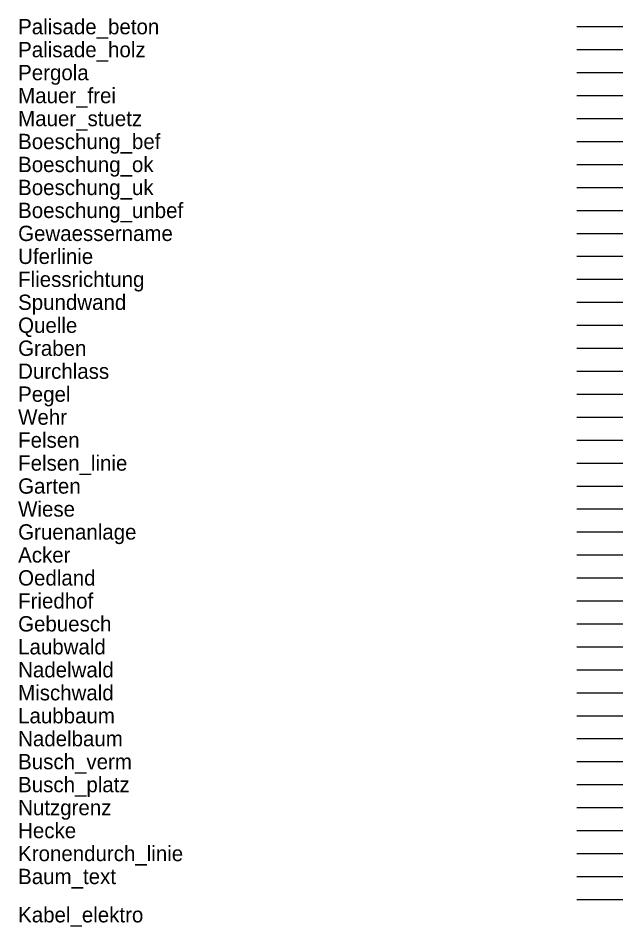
# Model space of a CAD drawing. Extents: x 0 to 177, y -135 to 1.
# Drawn here: x 83.5 to 123, y -58.8 to 0.6 of the extents above; entities that cross this region are included whole.
import ezdxf

# ---------------------------------------------------------------- set-up
doc = ezdxf.new("R2010")
doc.units = 0
for name, color, linetype in [('Acker', 7, 'Continuous'), ('Auslauf_schacht', 7, 'Continuous'), ('Baum_text', 7, 'Continuous'), ('Be_entlueftung', 7, 'Continuous'), ('Beobrohr_gw', 7, 'Continuous'), ('Boeschung_bef', 7, 'Continuous'), ('Boeschung_ok', 7, 'Continuous'), ('Boeschung_uk', 7, 'Continuous'), ('Boeschung_unbef', 7, 'Continuous'), ('Brunnen_eckig', 7, 'Continuous'), ('Brunnen_linie', 7, 'Continuous'), ('Brunnen_rund', 7, 'Continuous'), ('Busch_platz', 7, 'Continuous'), ('Busch_verm', 7, 'Continuous'), ('Durchlass', 7, 'Continuous'), ('Einlauf', 7, 'Continuous'), ('Einlauf_schacht', 7, 'Continuous'), ('Felsen', 7, 'Continuous'), ('Felsen_linie', 7, 'Continuous'), ('Fliessrichtung', 7, 'Continuous'), ('Friedhof', 7, 'Continuous'), ('Garten', 7, 'Continuous'), ('Gebuesch', 7, 'Continuous'), ('Gewaessername', 7, 'Continuous'), ('Graben', 7, 'Continuous'), ('Gruenanlage', 7, 'Continuous'), ('Gully', 7, 'Continuous'), ('Gullyrinne', 7, 'Continuous'), ('Hecke', 7, 'Continuous'), ('Kabel_elektro', 7, 'Continuous'), ('Klaeranlage', 7, 'Continuous'), ('Kronendurch_linie', 7, 'Continuous'), ('Laubbaum', 7, 'Continuous'), ('Laubwald', 7, 'Continuous'), ('Mauer_frei', 7, 'Continuous'), ('Mauer_stuetz', 7, 'Continuous'), ('Merkstein_wasser', 7, 'Continuous'), ('Mischwald', 7, 'Continuous'), ('Nadelbaum', 7, 'Continuous'), ('Nadelwald', 7, 'Continuous'), ('Nutzgrenz', 7, 'Continuous'), ('Oberflurhydrant', 7, 'Continuous'), ('Oedland', 7, 'Continuous'), ('Palisade_beton', 7, 'Continuous'), ('Palisade_holz', 7, 'Continuous'), ('Pegel', 7, 'Continuous'), ('Pergola', 7, 'Continuous'), ('Pfeil_abwasser', 7, 'Continuous'), ('Pfeil_brauchwasser', 7, 'Continuous'), ('Pfeil_regenwasser', 7, 'Continuous'), ('Pfeil_trinkwasser', 7, 'Continuous'), ('Pumpe', 7, 'Continuous'), ('Quelle', 7, 'Continuous'), ('Rohr_abwa', 7, 'Continuous'), ('Rohr_rewa', 7, 'Continuous'), ('Rohr_triwa', 7, 'Continuous'), ('Schacht_e_wasser', 7, 'Continuous'), ('Schacht_r_wasser', 7, 'Continuous'), ('Schieber_wasser', 7, 'Continuous'), ('Schrift_w', 7, 'Continuous'), ('Schrift_wb', 7, 'Continuous'), ('Schutzrohr_triwa', 7, 'Continuous'), ('Sohle_schacht', 7, 'Continuous'), ('Sonstiges_wasser', 7, 'Continuous'), ('Springbrunnen', 7, 'Continuous'), ('Spundwand', 7, 'Continuous'), ('Text_gullyrinne', 7, 'Continuous'), ('Text_rohr_abwa', 7, 'Continuous'), ('Text_rohr_rewa', 7, 'Continuous'), ('Text_rohr_triwa', 7, 'Continuous'), ('Text_schutzrohr_triwa', 7, 'Continuous'), ('Uferlinie', 7, 'Continuous'), ('Unterflurhydrant', 7, 'Continuous'), ('Wasserbehaelter_eckig', 7, 'Continuous'), ('Wasserbehaelter_rund', 7, 'Continuous'), ('Wehr', 7, 'Continuous'), ('Wiese', 7, 'Continuous'), ('Zapfstelle', 7, 'Continuous')]:
    doc.layers.add(name, color=color, linetype=linetype)

msp = doc.modelspace()

# ---------------------------------------------------------------- linework, layer by layer
at = {"layer": 'Auslauf_schacht'}
msp.add_line((120, -48), (123, -48), dxfattribs=at)
at = {"layer": 'Be_entlueftung'}
msp.add_line((120, -19.5), (123, -19.5), dxfattribs=at)
at = {"layer": 'Beobrohr_gw'}
msp.add_line((120, -18), (123, -18), dxfattribs=at)
at = {"layer": 'Brunnen_eckig'}
msp.add_line((120, -36), (123, -36), dxfattribs=at)
at = {"layer": 'Brunnen_linie'}
msp.add_line((120, -33), (123, -33), dxfattribs=at)
at = {"layer": 'Brunnen_rund'}
msp.add_line((120, -34.5), (123, -34.5), dxfattribs=at)
at = {"layer": 'Einlauf'}
msp.add_line((120, -28.5), (123, -28.5), dxfattribs=at)
at = {"layer": 'Einlauf_schacht'}
msp.add_line((120, -46.5), (123, -46.5), dxfattribs=at)
at = {"layer": 'Gully'}
msp.add_line((120, -27), (123, -27), dxfattribs=at)
at = {"layer": 'Gullyrinne'}
msp.add_line((120, -30), (123, -30), dxfattribs=at)
at = {"layer": 'Klaeranlage'}
msp.add_line((120, -43.5), (123, -43.5), dxfattribs=at)
at = {"layer": 'Merkstein_wasser'}
msp.add_line((120, -6), (123, -6), dxfattribs=at)
at = {"layer": 'Oberflurhydrant'}
msp.add_line((120, -12), (123, -12), dxfattribs=at)
at = {"layer": 'Pfeil_abwasser'}
msp.add_line((120, -45), (123, -45), dxfattribs=at)
at = {"layer": 'Pfeil_brauchwasser'}
msp.add_line((120, -54), (123, -54), dxfattribs=at)
at = {"layer": 'Pfeil_regenwasser'}
msp.add_line((120, -55.5), (123, -55.5), dxfattribs=at)
at = {"layer": 'Pfeil_trinkwasser'}
msp.add_line((120, -9), (123, -9), dxfattribs=at)
at = {"layer": 'Pumpe'}
msp.add_line((120, -39), (123, -39), dxfattribs=at)
at = {"layer": 'Rohr_abwa'}
msp.add_line((120, -40.5), (123, -40.5), dxfattribs=at)
at = {"layer": 'Rohr_rewa'}
msp.add_line((120, -51), (123, -51), dxfattribs=at)
at = {"layer": 'Rohr_triwa'}
msp.add_line((120, 0), (123, 0), dxfattribs=at)
at = {"layer": 'Schacht_e_wasser'}
msp.add_line((120, -16.5), (123, -16.5), dxfattribs=at)
at = {"layer": 'Schacht_r_wasser'}
msp.add_line((120, -15), (123, -15), dxfattribs=at)
at = {"layer": 'Schieber_wasser'}
msp.add_line((120, -10.5), (123, -10.5), dxfattribs=at)
at = {"layer": 'Schrift_w'}
msp.add_line((120, -7.5), (123, -7.5), dxfattribs=at)
at = {"layer": 'Schrift_wb'}
msp.add_line((120, -25.5), (123, -25.5), dxfattribs=at)
at = {"layer": 'Schutzrohr_triwa'}
msp.add_line((120, -3), (123, -3), dxfattribs=at)
at = {"layer": 'Sohle_schacht'}
msp.add_line((120, -49.5), (123, -49.5), dxfattribs=at)
at = {"layer": 'Sonstiges_wasser'}
msp.add_line((120, -57), (123, -57), dxfattribs=at)
at = {"layer": 'Springbrunnen'}
msp.add_line((120, -37.5), (123, -37.5), dxfattribs=at)
at = {"layer": 'Text_gullyrinne'}
msp.add_line((120, -31.5), (123, -31.5), dxfattribs=at)
at = {"layer": 'Text_rohr_abwa'}
msp.add_line((120, -42), (123, -42), dxfattribs=at)
at = {"layer": 'Text_rohr_rewa'}
msp.add_line((120, -52.5), (123, -52.5), dxfattribs=at)
at = {"layer": 'Text_rohr_triwa'}
msp.add_line((120, -1.5), (123, -1.5), dxfattribs=at)
at = {"layer": 'Text_schutzrohr_triwa'}
msp.add_line((120, -4.5), (123, -4.5), dxfattribs=at)
at = {"layer": 'Unterflurhydrant'}
msp.add_line((120, -13.5), (123, -13.5), dxfattribs=at)
at = {"layer": 'Wasserbehaelter_eckig'}
msp.add_line((120, -24), (123, -24), dxfattribs=at)
at = {"layer": 'Wasserbehaelter_rund'}
msp.add_line((120, -22.5), (123, -22.5), dxfattribs=at)
at = {"layer": 'Zapfstelle'}
msp.add_line((120, -21), (123, -21), dxfattribs=at)

# ---------------------------------------------------------------- texts
at = {"layer": 'Acker'}
msp.add_text('Acker', height=1, dxfattribs=at).set_placement((83.5, -35))
at = {"layer": 'Baum_text'}
msp.add_text('Baum_text', height=1, dxfattribs=at).set_placement((83.5, -56))
at = {"layer": 'Boeschung_bef'}
msp.add_text('Boeschung_bef', height=1, dxfattribs=at).set_placement((83.5, -8))
at = {"layer": 'Boeschung_ok'}
msp.add_text('Boeschung_ok', height=1, dxfattribs=at).set_placement((83.5, -9.5))
at = {"layer": 'Boeschung_uk'}
msp.add_text('Boeschung_uk', height=1, dxfattribs=at).set_placement((83.5, -11))
at = {"layer": 'Boeschung_unbef'}
msp.add_text('Boeschung_unbef', height=1, dxfattribs=at).set_placement((83.5, -12.5))
at = {"layer": 'Busch_platz'}
msp.add_text('Busch_platz', height=1, dxfattribs=at).set_placement((83.5, -50))
at = {"layer": 'Busch_verm'}
msp.add_text('Busch_verm', height=1, dxfattribs=at).set_placement((83.5, -48.5))
at = {"layer": 'Durchlass'}
msp.add_text('Durchlass', height=1, dxfattribs=at).set_placement((83.5, -23))
at = {"layer": 'Felsen'}
msp.add_text('Felsen', height=1, dxfattribs=at).set_placement((83.5, -27.5))
at = {"layer": 'Felsen_linie'}
msp.add_text('Felsen_linie', height=1, dxfattribs=at).set_placement((83.5, -29))
at = {"layer": 'Fliessrichtung'}
msp.add_text('Fliessrichtung', height=1, dxfattribs=at).set_placement((83.5, -17))
at = {"layer": 'Friedhof'}
msp.add_text('Friedhof', height=1, dxfattribs=at).set_placement((83.5, -38))
at = {"layer": 'Garten'}
msp.add_text('Garten', height=1, dxfattribs=at).set_placement((83.5, -30.5))
at = {"layer": 'Gebuesch'}
msp.add_text('Gebuesch', height=1, dxfattribs=at).set_placement((83.5, -39.5))
at = {"layer": 'Gewaessername'}
msp.add_text('Gewaessername', height=1, dxfattribs=at).set_placement((83.5, -14))
at = {"layer": 'Graben'}
msp.add_text('Graben', height=1, dxfattribs=at).set_placement((83.5, -21.5))
at = {"layer": 'Gruenanlage'}
msp.add_text('Gruenanlage', height=1, dxfattribs=at).set_placement((83.5, -33.5))
at = {"layer": 'Hecke'}
msp.add_text('Hecke', height=1, dxfattribs=at).set_placement((83.5, -53))
at = {"layer": 'Kabel_elektro'}
msp.add_text('Kabel_elektro', height=1, dxfattribs=at).set_placement((83.5, -58.5))
at = {"layer": 'Kronendurch_linie'}
msp.add_text('Kronendurch_linie', height=1, dxfattribs=at).set_placement((83.5, -54.5))
at = {"layer": 'Laubbaum'}
msp.add_text('Laubbaum', height=1, dxfattribs=at).set_placement((83.5, -45.5))
at = {"layer": 'Laubwald'}
msp.add_text('Laubwald', height=1, dxfattribs=at).set_placement((83.5, -41))
at = {"layer": 'Mauer_frei'}
msp.add_text('Mauer_frei', height=1, dxfattribs=at).set_placement((83.5, -5))
at = {"layer": 'Mauer_stuetz'}
msp.add_text('Mauer_stuetz', height=1, dxfattribs=at).set_placement((83.5, -6.5))
at = {"layer": 'Mischwald'}
msp.add_text('Mischwald', height=1, dxfattribs=at).set_placement((83.5, -44))
at = {"layer": 'Nadelbaum'}
msp.add_text('Nadelbaum', height=1, dxfattribs=at).set_placement((83.5, -47))
at = {"layer": 'Nadelwald'}
msp.add_text('Nadelwald', height=1, dxfattribs=at).set_placement((83.5, -42.5))
at = {"layer": 'Nutzgrenz'}
msp.add_text('Nutzgrenz', height=1, dxfattribs=at).set_placement((83.5, -51.5))
at = {"layer": 'Oedland'}
msp.add_text('Oedland', height=1, dxfattribs=at).set_placement((83.5, -36.5))
at = {"layer": 'Palisade_beton'}
msp.add_text('Palisade_beton', height=1, dxfattribs=at).set_placement((83.5, -0.5))
at = {"layer": 'Palisade_holz'}
msp.add_text('Palisade_holz', height=1, dxfattribs=at).set_placement((83.5, -2))
at = {"layer": 'Pegel'}
msp.add_text('Pegel', height=1, dxfattribs=at).set_placement((83.5, -24.5))
at = {"layer": 'Pergola'}
msp.add_text('Pergola', height=1, dxfattribs=at).set_placement((83.5, -3.5))
at = {"layer": 'Quelle'}
msp.add_text('Quelle', height=1, dxfattribs=at).set_placement((83.5, -20))
at = {"layer": 'Spundwand'}
msp.add_text('Spundwand', height=1, dxfattribs=at).set_placement((83.5, -18.5))
at = {"layer": 'Uferlinie'}
msp.add_text('Uferlinie', height=1, dxfattribs=at).set_placement((83.5, -15.5))
at = {"layer": 'Wehr'}
msp.add_text('Wehr', height=1, dxfattribs=at).set_placement((83.5, -26))
at = {"layer": 'Wiese'}
msp.add_text('Wiese', height=1, dxfattribs=at).set_placement((83.5, -32))

doc.saveas('drawing.dxf')
